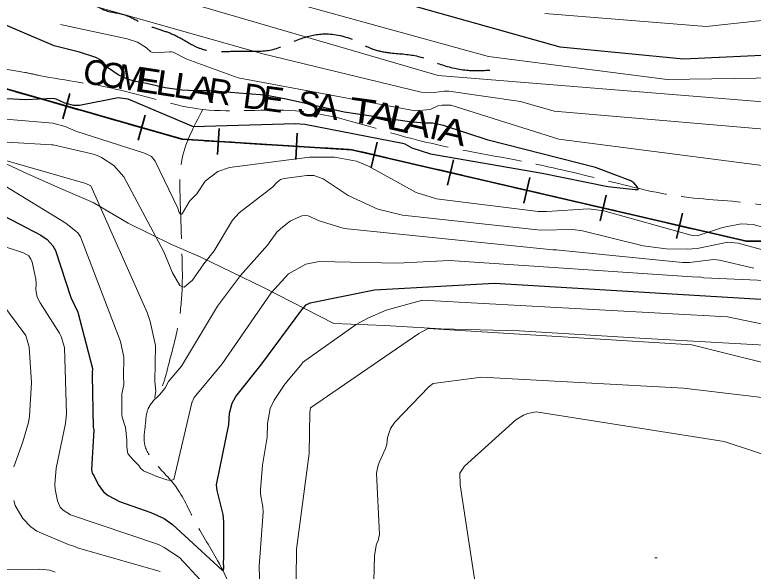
# Model space of a CAD drawing. Extents: x 483843 to 488449, y 4381269 to 4384483.
# Drawn here: x 485396.9 to 485679.6, y 4383054.9 to 4383267.6 of the extents above; entities that cross this region are included whole.
import ezdxf
from ezdxf.enums import TextEntityAlignment as Align

# ---------------------------------------------------------------- set-up
doc = ezdxf.new("R2010")
doc.units = 0
doc.header["$LTSCALE"] = 3.8
doc.linetypes.add('LONG_DASHED', pattern=[7.5, 6, -1.5])
for name, color, linetype, lineweight in [('15', 7, 'LONG_DASHED', 13), ('34', 7, 'Continuous', 35), ('38', 7, 'Continuous', 25), ('51', 7, 'Continuous', 13), ('7', 7, 'Continuous', 13), ('8', 7, 'Continuous', 25), ('9', 7, 'Continuous', 13)]:
    doc.layers.add(name, color=color, linetype=linetype, lineweight=lineweight)
doc.layers.add('5', color=7, linetype='Continuous')

msp = doc.modelspace()

# ---------------------------------------------------------------- linework, layer by layer
at = {"layer": '15'}
for points in [[(485400.79, 4383245.56), (485366.79, 4383254.46), (485349.06, 4383265.95), (485335.06, 4383279.34), (485325.06, 4383291.04), (485319.26, 4383301.47), (485316.79, 4383311.82), (485317.67, 4383326.99), (485317.51, 4383342.72), (485315.45, 4383356.54), (485311.11, 4383375.24), (485304.67, 4383396.11), (485302.81, 4383413.58), (485295.88, 4383427.71), (485283.48, 4383443.67), (485274.41, 4383458.47), (485261.63, 4383473.96), (485248.35, 4383487.62), (485231.39, 4383496.46), (485206.95, 4383503.97), (485193.14, 4383504.9), (485172.81, 4383504.39), (485157.78, 4383504.12), (485145.67, 4383503.51), (485134.2, 4383504.43), (485123.74, 4383508.44), (485114.92, 4383511.93), (485112.2, 4383519.17), (485112.66, 4383528.99), (485114.36, 4383533.28), (485118.17, 4383541.74), (485121.31, 4383564.66), (485114.52, 4383595.67), (485109.69, 4383608.55), (485102.62, 4383619.36), (485089.28, 4383632.72), (485077.31, 4383638.83), (485057.92, 4383643.83), (485043.91, 4383643.5), (485030.6, 4383637.83), (485020.31, 4383630.47), (485011.46, 4383621.88), (484999.37, 4383601.37), (484981.13, 4383564.54), (484972.78, 4383546.81), (484964.72, 4383533.9), (484948.73, 4383515.05), (484938.85, 4383501.38), (484922.26, 4383484.64), (484903.34, 4383464.23), (484878.47, 4383440.05), (484853, 4383412.61), (484831.2, 4383387.67), (484805.14, 4383358.11), (484790.45, 4383334.7), (484768.3, 4383297.93), (484757.66, 4383281.26), (484749.41, 4383271.28), (484740.24, 4383261.88), (484732.92, 4383256.49), (484722.63, 4383254.85), (484718.27, 4383254.66), (484706.61, 4383259.28), (484700.75, 4383263.84), (484695.83, 4383273.7), (484694.44, 4383282.5), (484695.04, 4383297.06), (484696.68, 4383304.96), (484697.51, 4383309.13), (484702.36, 4383327.31), (484705.59, 4383338.26)], [(485400.79, 4383245.56), (485406.29, 4383244.41), (485437.45, 4383238.77), (485468.96, 4383231.4), (485504.33, 4383230.87), (485548.91, 4383220.24), (485591.04, 4383211.58), (485622.86, 4383204.36), (485651.32, 4383198.17), (485680.8, 4383195.25), (485706.08, 4383191.57), (485722.37, 4383193.95), (485735.23, 4383201.55), (485745.53, 4383213.76), (485759.02, 4383234.02), (485775.19, 4383262.78), (485795.18, 4383296.65), (485816.27, 4383323.61), (485841.16, 4383349.54), (485867.84, 4383369.45), (485913.47, 4383388.85), (485935.22, 4383394.97), (485958.89, 4383388.99), (485973.47, 4383381.81), (485979.32, 4383377.07), (485984.47, 4383370.85), (485987.04, 4383362.27), (485987.36, 4383354.02), (485987.36, 4383343.75), (485982.84, 4383337.15), (485969.6, 4383328.73), (485958.55, 4383321.85), (485945.63, 4383309.53), (485931.32, 4383300.15), (485906.76, 4383286.36), (485891.85, 4383276.39), (485880.57, 4383264.12), (485871.36, 4383244.47), (485865.12, 4383222.84), (485860.75, 4383191.43), (485865.12, 4383163.11), (485877.56, 4383143.14), (485893.96, 4383132.18), (485911.26, 4383131.69), (485923.31, 4383135.71), (485933.99, 4383143.04), (485949.29, 4383153.83), (485962.9, 4383167.19), (485985.6, 4383171.87), (486005.81, 4383170.22), (486029.34, 4383160.05), (486043.95, 4383149.41), (486042.89, 4383138.86), (486041.88, 4383131.75), (486041.4, 4383119.4), (486046.63, 4383078.7), (486048.42, 4383062.79), (486056.08, 4383044.24), (486065.61, 4383030.31), (486078.82, 4383011.67), (486095.82, 4382995.68), (486117.1, 4382985.39), (486141.45, 4382970.26), (486161.85, 4382961.49), (486185.85, 4382957.83), (486221.05, 4382956.33), (486256.43, 4382956.62), (486292.45, 4382960.13), (486324.15, 4382965.13)], [(485468.96, 4383231.4), (485460.69, 4383211.27), (485460.2, 4383198), (485460.93, 4383175.7), (485460.86, 4383160.24), (485459.09, 4383147.06), (485455.67, 4383133.31), (485454.08, 4383127.48), (485451.99, 4383122.7), (485447.85, 4383116.61), (485446.95, 4383111.22), (485446.61, 4383103.5), (485450.56, 4383096.39), (485458.98, 4383086.59), (485466.21, 4383073.2), (485474.56, 4383058.98), (485485.59, 4383037.51), (485498.24, 4383019.77), (485503.2, 4383004.31), (485505.84, 4382984.84), (485514.14, 4382961.84)]]:
    msp.add_spline(points, degree=3, dxfattribs=at)
at = {"layer": '34'}
for p, q in [((485397.44, 4383238.16), (485407.06, 4383235.41)), ((485418.04, 4383237.47), (485415.29, 4383227.86)), ((485411.86, 4383234.04), (485421.47, 4383231.29)), ((485426.28, 4383229.92), (485435.9, 4383227.17)), ((485446.87, 4383229.24), (485444.13, 4383219.62)), ((485440.69, 4383225.8), (485450.31, 4383223.05)), ((485475.15, 4383224.14), (485474.54, 4383214.16)), ((485505.08, 4383222.3), (485504.47, 4383212.32)), ((485469.85, 4383219.46), (485479.83, 4383218.84)), ((485484.83, 4383218.53), (485494.81, 4383217.92)), ((485535.63, 4383218.9), (485533.37, 4383209.16)), ((485499.79, 4383217.61), (485509.77, 4383217)), ((485514.76, 4383216.69), (485524.74, 4383216.08)), ((485529.63, 4383215.16), (485539.37, 4383212.9)), ((485564.85, 4383212.13), (485562.59, 4383202.39)), ((485544.24, 4383211.77), (485553.99, 4383209.51)), ((485558.85, 4383208.39), (485568.59, 4383206.13)), ((485573.46, 4383205), (485583.2, 4383202.74)), ((485594.06, 4383205.36), (485591.8, 4383195.61)), ((485588.06, 4383201.61), (485597.8, 4383199.36)), ((485602.67, 4383198.23), (485612.42, 4383195.97)), ((485623.28, 4383198.58), (485621.02, 4383188.84)), ((485617.28, 4383194.84), (485627.02, 4383192.58)), ((485631.89, 4383191.46), (485641.63, 4383189.2)), ((485652.49, 4383191.81), (485650.23, 4383182.07)), ((485646.49, 4383188.07), (485656.23, 4383185.81)), ((485661.11, 4383184.68), (485670.85, 4383182.43))]:
    msp.add_line(p, q, dxfattribs=at)
for points in [[(485328, 4383258), (485461, 4383220), (485526, 4383216), (485677, 4383181), (485719, 4383181)], [(485455.12, 4383221.68), (485461, 4383220), (485464.87, 4383219.76)], [(485675.71, 4383181.3), (485677, 4383181), (485685.67, 4383181)]]:
    msp.add_lwpolyline(points, dxfattribs=at)
at = {"layer": '38', "linetype": 'LONG_DASHED'}
msp.add_spline([(485401.58, 4383291.23), (485405.77, 4383290.32), (485409.93, 4383287.49), (485412.44, 4383284.9), (485419.2, 4383280.22), (485424.24, 4383275.72), (485426.89, 4383272.39), (485430.91, 4383269.55), (485439.06, 4383267.56), (485445.84, 4383264.31), (485452.11, 4383262.04), (485457.56, 4383260.09), (485464.63, 4383256.24), (485469.33, 4383254.29), (485475.7, 4383253.6), (485484.78, 4383253.7), (485495.14, 4383254.22), (485505.55, 4383258.13), (485514.74, 4383260.25), (485526.41, 4383258.05), (485534.02, 4383254.49), (485540.82, 4383253.05), (485551.38, 4383251.69), (485559.97, 4383248.64), (485570.52, 4383246.39), (485578.77, 4383246.42)], degree=3, dxfattribs=at)
at = {"layer": '51'}
for points in [[(485400.13, 4383207.61), (485339.93, 4383235.81), (485304.61, 4383259.5), (485273.66, 4383308.81), (485237.83, 4383336.45), (485231.15, 4383332), (485147.19, 4383369.84), (485053.5, 4383411.23), (485019.48, 4383420.27), (484981.87, 4383400.27), (484953.62, 4383385.83), (484933.81, 4383374.86), (484903, 4383358.06), (484866.78, 4383335.14), (484831.69, 4383306.08), (484808.69, 4383288.72)], [(485400.13, 4383207.61), (485400.68, 4383207.33), (485415.36, 4383200.74), (485426.92, 4383195.77), (485440.32, 4383187.93), (485456.93, 4383179.81), (485467.9, 4383175.08), (485492.19, 4383163.32), (485519.08, 4383149.58), (485538.51, 4383148.85), (485560.02, 4383147.57), (485590.1, 4383146.76), (485636.13, 4383143.93), (485683.89, 4383141.22)]]:
    msp.add_lwpolyline(points, dxfattribs=at)
at = {"layer": '7'}
msp.add_line((485641.86, 4383060.03), (485642.86, 4383060.03), dxfattribs=at)
at = {"layer": '8'}
for points in [[(485751.85, 4383289.93), (485715.54, 4383262.8), (485706.59, 4383257.49), (485699.49, 4383255.16), (485682.81, 4383252.04), (485652.91, 4383250.57), (485605.74, 4383255.17), (485481.55, 4383290.17), (485473.67, 4383293.3), (485456.27, 4383303.25), (485440.6, 4383324.41), (485408.45, 4383384.34), (485404.48, 4383395.71), (485398.47, 4383418.32), (485391.87, 4383434.28)], [(485411.06, 4383256.08), (485387.4, 4383266.22)], [(485432.84, 4383247.22), (485430.69, 4383249.62), (485429.38, 4383250.52), (485427.95, 4383251.31), (485421.73, 4383253.33), (485411.95, 4383255.7), (485411.06, 4383256.08)], [(485598.81, 4383207.07), (485623.98, 4383201.92), (485634.38, 4383200.79), (485635.51, 4383200.79), (485635.51, 4383201.08), (485635.23, 4383201.64), (485633.82, 4383203.33), (485632.7, 4383204.17), (485619.2, 4383209.23), (485578.15, 4383219.64), (485561, 4383225.27), (485556.78, 4383226.11), (485553.69, 4383226.11), (485548.07, 4383226.67), (485523.04, 4383230.33), (485500.83, 4383235.39), (485492.68, 4383236.8), (485485.93, 4383237.36), (485479.46, 4383237.93), (485471.31, 4383238.49), (485466.25, 4383238.49), (485460.9, 4383238.77), (485454.44, 4383239.61), (485447.41, 4383241.3), (485443.19, 4383242.15), (485440.1, 4383242.99), (485436.44, 4383244.68), (485432.84, 4383247.22)], [(485381.79, 4383236.28), (485401.16, 4383235.22), (485411.64, 4383235.74), (485412.69, 4383235.45), (485416.02, 4383233.92), (485419.35, 4383233.05), (485421.64, 4383233.04), (485436.48, 4383236.02), (485440.21, 4383235.45), (485465.25, 4383224.86), (485504.28, 4383226.03), (485507.97, 4383225.72), (485545.37, 4383218.53), (485546.25, 4383218.23), (485548.94, 4383216.74), (485556.01, 4383214.42), (485598.81, 4383207.07)], [(485313.52, 4383231.99), (485406.85, 4383183.29), (485409.33, 4383181.64), (485411.55, 4383179.27), (485412.55, 4383177.45), (485418.4, 4383159.47), (485421.1, 4383153.93), (485426.63, 4383132.3), (485426.6, 4383130.7), (485426.63, 4383130.23), (485426.61, 4383130.08), (485426.53, 4383129.79), (485426.89, 4383109.82), (485427.02, 4383109.49), (485427.16, 4383108.79), (485426.35, 4383093.76), (485426.56, 4383092.3), (485427.13, 4383091.43), (485428.81, 4383088), (485430.91, 4383085.16), (485432.67, 4383083.77), (485436.96, 4383081.54), (485449.05, 4383077.31), (485454.06, 4383074.95), (485457.3, 4383072.73), (485476.31, 4383055.24), (485476.52, 4383055.17), (485476.69, 4383055.19), (485476.92, 4383056.06), (485476.84, 4383058.68), (485476.9, 4383059.39), (485476.95, 4383059.67), (485476.97, 4383073.74), (485476.64, 4383076.52), (485474.34, 4383085.7), (485474.2, 4383087.93), (485478.8, 4383110.9), (485479.18, 4383115.27), (485480.15, 4383119.16), (485481.5, 4383121.67), (485491.07, 4383133.58), (485506.85, 4383154.85), (485508.48, 4383156.64), (485509.44, 4383157.25), (485509.96, 4383157.47), (485534.58, 4383162.45), (485580.59, 4383164.98), (485701.63, 4383157.72)]]:
    msp.add_lwpolyline(points, dxfattribs=at)
at = {"layer": '9'}
for points in [[(485706.31, 4383243.8), (485646.64, 4383242.79), (485578.25, 4383251.69), (485453.63, 4383286), (485447.32, 4383288.5), (485412.84, 4383321.84), (485411.03, 4383324.65), (485410.42, 4383326.19)], [(485789.46, 4383314.41), (485765.49, 4383282.39), (485760.82, 4383277.45), (485732.51, 4383255.64), (485727.24, 4383250.07), (485726.52, 4383249.08), (485725.17, 4383246.15), (485724.5, 4383243.69), (485723.87, 4383242.29), (485722.29, 4383239.73), (485719.79, 4383237.32), (485717.87, 4383236.14), (485713.42, 4383234.3), (485707.67, 4383233.19), (485703.9, 4383233.04), (485681.77, 4383234.41), (485559.03, 4383244.42), (485439.39, 4383279.3), (485432.11, 4383282.68), (485419.75, 4383290.44), (485412.61, 4383296.95), (485405.9, 4383304.82), (485399.99, 4383314.38), (485394.9, 4383325.02)], [(485718.02, 4383224.47), (485708.03, 4383222.54), (485701.48, 4383222.28), (485603.34, 4383230.73), (485590.56, 4383234.5), (485563.04, 4383238.35), (485561.26, 4383238.41), (485557.51, 4383237.9), (485552.52, 4383238.05), (485491.85, 4383252.63), (485419.3, 4383273.23), (485412.39, 4383276.1), (485404.95, 4383280.59), (485402.48, 4383282.64), (485400, 4383285.87), (485395.79, 4383292.85)], [(485599.75, 4383268.07), (485661.56, 4383263.16), (485705.28, 4383267.88)], [(485715.78, 4383208.19), (485712.84, 4383207.07), (485709.7, 4383206.47), (485605.15, 4383220.02), (485563.79, 4383233.07), (485560.56, 4383233.09), (485558.87, 4383232.73), (485555.98, 4383231.37), (485550.19, 4383230.84), (485482.39, 4383243.47), (485462.78, 4383250.59), (485457.54, 4383253.26), (485456.87, 4383253.38), (485456.15, 4383253.45), (485450.3, 4383253.03), (485449.65, 4383253.18), (485449.05, 4383253.42), (485447.41, 4383254.96), (485443.88, 4383257.11), (485439.96, 4383258.35), (485414.42, 4383263.92)], [(485385.86, 4383228.3), (485411.55, 4383226.12), (485416.17, 4383224.9), (485420.33, 4383223.11), (485446.54, 4383214.69), (485449.24, 4383213.4), (485450.66, 4383211.62), (485459.38, 4383193.65), (485459.9, 4383192.04), (485460.51, 4383191.25), (485460.73, 4383191.33), (485460.99, 4383191.53), (485463.71, 4383196.12), (485464.04, 4383196.57), (485466.6, 4383199.15), (485469.86, 4383203.97), (485474.6, 4383207.62), (485479.13, 4383209.26), (485509.77, 4383213.2), (485519.35, 4383213.14), (485527.76, 4383211.57), (485532.3, 4383209.77), (485550.53, 4383199.59), (485558.29, 4383197.28), (485597.2, 4383192.4), (485600.55, 4383192.34), (485616.59, 4383193.44), (485622.39, 4383192.6), (485656.17, 4383183.23), (485658.12, 4383183.1), (485667.77, 4383186.31), (485675, 4383187.69), (485679.49, 4383187.47), (485703.39, 4383180.62)], [(485368, 4383219.18), (485424.15, 4383203.06), (485426.06, 4383202.17), (485447.66, 4383153.77), (485448.8, 4383150.29), (485450.76, 4383141.18), (485450.52, 4383127.39), (485450.87, 4383123.65), (485450.84, 4383122.78), (485450.6, 4383121.45), (485450.65, 4383120.88), (485450.81, 4383120.93), (485451.04, 4383121.08), (485452.41, 4383122.38), (485454.23, 4383124.54), (485454.51, 4383124.93), (485455.83, 4383127.42), (485460.7, 4383133.19), (485474.5, 4383156.25), (485483.27, 4383167.95), (485493.71, 4383179.46), (485497.19, 4383184.45), (485498.71, 4383185.91), (485502.48, 4383188.82), (485506.85, 4383190.71), (485508.04, 4383190.81), (485509.21, 4383190.72), (485513.39, 4383188.88), (485523.05, 4383185.85), (485602.89, 4383177.69), (485604.26, 4383177.73), (485605.34, 4383177.56), (485652.48, 4383172.88), (485655.13, 4383172.87), (485664.39, 4383174.02), (485666.64, 4383173.83), (485679.87, 4383170.68)], [(485394.03, 4383218.93), (485410.93, 4383217.93), (485411.66, 4383217.82), (485427.6, 4383214.14), (485430.08, 4383213.03), (485434.82, 4383209.92), (485438.67, 4383205.69), (485454.01, 4383176.98), (485457.32, 4383168.95), (485460.13, 4383164.08), (485460.95, 4383163.59), (485461.78, 4383163.46), (485464.92, 4383166.1), (485469.26, 4383172.41), (485473.26, 4383177.3), (485480.29, 4383189.12), (485482.77, 4383191.83), (485495.54, 4383201.75), (485497.35, 4383203.55), (485498.7, 4383204.59), (485499.99, 4383205.06), (485508.71, 4383206.18), (485511.44, 4383206.16), (485514.93, 4383204.91), (485524.5, 4383198.55), (485535.93, 4383193.34), (485545.39, 4383190.98), (485598.15, 4383185.2), (485610.56, 4383185.55), (485614.2, 4383184.98), (485637.45, 4383179.27), (485646.31, 4383178.12), (485654.25, 4383177.94), (485658.07, 4383178.29), (485669.87, 4383180.67)], [(485393.08, 4383202.18), (485416.42, 4383187.9), (485420.48, 4383184.7), (485421.03, 4383184.17), (485422.04, 4383182.76), (485437.34, 4383142.69), (485438.69, 4383136.74), (485438.56, 4383129.05), (485438.7, 4383126.79), (485438.61, 4383126.07), (485437.87, 4383122.71), (485437.86, 4383115.01), (485438.04, 4383113.69), (485439.32, 4383109.76), (485439.85, 4383105.1), (485439.78, 4383102.45), (485440.04, 4383100.44), (485440.26, 4383099.9), (485440.54, 4383099.37), (485442.09, 4383097.53), (485444.37, 4383095.22), (485445.04, 4383094.26), (485446.21, 4383093.29), (485451.3, 4383091.01), (485455.07, 4383089.77), (485456.49, 4383089.55), (485457.81, 4383089.98), (485464.64, 4383119.23), (485465.56, 4383121.29), (485476.28, 4383134.14), (485495.11, 4383161.32), (485501.68, 4383168.59), (485508.29, 4383172.28), (485513.46, 4383173.3), (485543.35, 4383172.61), (485563.36, 4383173.71), (485658.08, 4383167.24), (485658.91, 4383167.38), (485659.46, 4383167.33), (485660.62, 4383167.03), (485701.77, 4383165.27)], [(485476.1, 4383042.81), (485459.97, 4383060.13), (485454.14, 4383063.98), (485451.95, 4383065.03), (485418.24, 4383076.4), (485415.41, 4383078.22), (485414.83, 4383078.79), (485414.34, 4383079.39), (485413.32, 4383081.81), (485412.36, 4383086.22), (485412.23, 4383087.96), (485412.79, 4383094.27), (485416.32, 4383111.34), (485416.67, 4383115.04), (485416.01, 4383140.35), (485414.65, 4383144.54), (485414.03, 4383145.83), (485406.6, 4383157.5), (485405.55, 4383159.66), (485405.05, 4383162.45), (485405.18, 4383164.85), (485405.04, 4383166.46), (485403.53, 4383172.99), (485403.06, 4383174.19), (485402.25, 4383175.38), (485401.45, 4383175.91), (485400.21, 4383176.55), (485391.19, 4383179.56)], [(485669.87, 4383180.67), (485673.82, 4383180.34), (485694.31, 4383174.63)], [(485388.18, 4383162.35), (485401.21, 4383144.94), (485402.5, 4383140.5), (485403.31, 4383127), (485402.53, 4383114.14), (485402.13, 4383111.75), (485400.06, 4383104.37), (485396.56, 4383094.81)], [(485701.06, 4383145.64), (485669.74, 4383152.07), (485552.96, 4383158.45), (485539.08, 4383154.66), (485532.01, 4383151.65), (485527.66, 4383149.21), (485507.11, 4383134.59), (485506.88, 4383134.26), (485500.3, 4383126.34), (485496.16, 4383120.29), (485494.73, 4383117.03), (485493.71, 4383111.31), (485493.52, 4383106.05), (485491.78, 4383095.45), (485490.92, 4383085.92), (485491.02, 4383084.33), (485491.91, 4383079.53), (485492.02, 4383077.49)], [(485504.13, 4383005.09), (485504.8, 4383063.28), (485509.64, 4383099.8), (485509.81, 4383115.55), (485510.17, 4383117.32), (485551.63, 4383145.75), (485555.18, 4383147.66), (485656.11, 4383141.38), (485699.62, 4383130.57)], [(485533.24, 4383006.63), (485534.67, 4383060.88), (485535.39, 4383065.27), (485535.96, 4383066.46), (485536.21, 4383067.26), (485536.55, 4383068.94), (485535.35, 4383092.34), (485535.88, 4383094.92), (485536.38, 4383096.38), (485538.89, 4383101.82), (485539.31, 4383103.33), (485539.6, 4383106.02), (485540.74, 4383109.37), (485542.36, 4383111.79), (485555.37, 4383125.35), (485557.05, 4383126.57), (485575.54, 4383129.07)], [(485575.54, 4383129.07), (485652.95, 4383124.9), (485724.79, 4383116.36)], [(485563.54, 4382917.29), (485565.45, 4382920), (485572.9, 4382928), (485578.37, 4382935.32), (485580.48, 4382939.96), (485582.63, 4382949.41), (485583.04, 4382958.37), (485582.7, 4382962.34), (485581.05, 4382967.69), (485574.2, 4382983.92), (485571.84, 4382993.65), (485571.13, 4383000.09), (485573.2, 4383050.28), (485567.4, 4383087.87), (485567.31, 4383092.37), (485569.12, 4383095.04), (485588.7, 4383112.78), (485591.62, 4383114.51), (485593.32, 4383115.15), (485596.54, 4383115.76), (485668.51, 4383104.43), (485689.33, 4383097.6)], [(485396.61, 4383081.87), (485397.04, 4383079.98), (485400.01, 4383075), (485403.04, 4383071.78), (485405.39, 4383070.16), (485417.71, 4383064.91)], [(485492.02, 4383077.49), (485490.86, 4383061.85), (485490.47, 4383056.89), (485490.92, 4383038.17)], [(485417.71, 4383064.91), (485419.13, 4383064.5), (485419.56, 4383064.43), (485419.96, 4383064.26), (485420.94, 4383063.74), (485452.56, 4383054.72)], [(485382.31, 4383055.21), (485406.52, 4383055.68), (485410.33, 4383055.25), (485412.44, 4383054.55)]]:
    msp.add_lwpolyline(points, dxfattribs=at)

# ---------------------------------------------------------------- texts
at = {"layer": '5'}
for s, rotation, p in [('C', 351.299, (485427.1, 4383240.83)), ('O', 351.299, (485433.93, 4383239.78)), ('E', 351.299, (485447.56, 4383237.7)), ('R', 351.299, (485474.85, 4383233.52)), ('D', 352.456, (485488.4, 4383231.52)), ('S', 352.456, (485508.92, 4383228.8)), ('I', 346.997, (485556.86, 4383220.04))]:
    msp.add_text(s, height=9.49, rotation=rotation, dxfattribs=at).set_placement(p, align=Align.CENTER)
for s, rotation, width, p in [('M', 351.299, 0.95, (485440.75, 4383238.74)), ('L', 351.299, 1.15, (485454.44, 4383236.64)), ('L', 351.299, 1.15, (485461.26, 4383235.6)), ('A', 351.299, 1.15, (485468.02, 4383234.55)), ('E', 352.456, 0.95, (485495.23, 4383230.62)), ('A', 352.456, 1.1, (485515.75, 4383227.9)), ('T', 352.456, 1.3, (485529.45, 4383226.08)), ('A', 346.997, 1.25, (485536.69, 4383224.69)), ('L', 346.997, 1.25, (485543.46, 4383223.13)), ('A', 346.997, 1.25, (485550.14, 4383221.59)), ('A', 346.997, 1.25, (485563.58, 4383218.48))]:
    msp.add_text(s, height=9.49, rotation=rotation, dxfattribs=dict(at, width=width)).set_placement(p, align=Align.CENTER)

doc.saveas('drawing.dxf')
